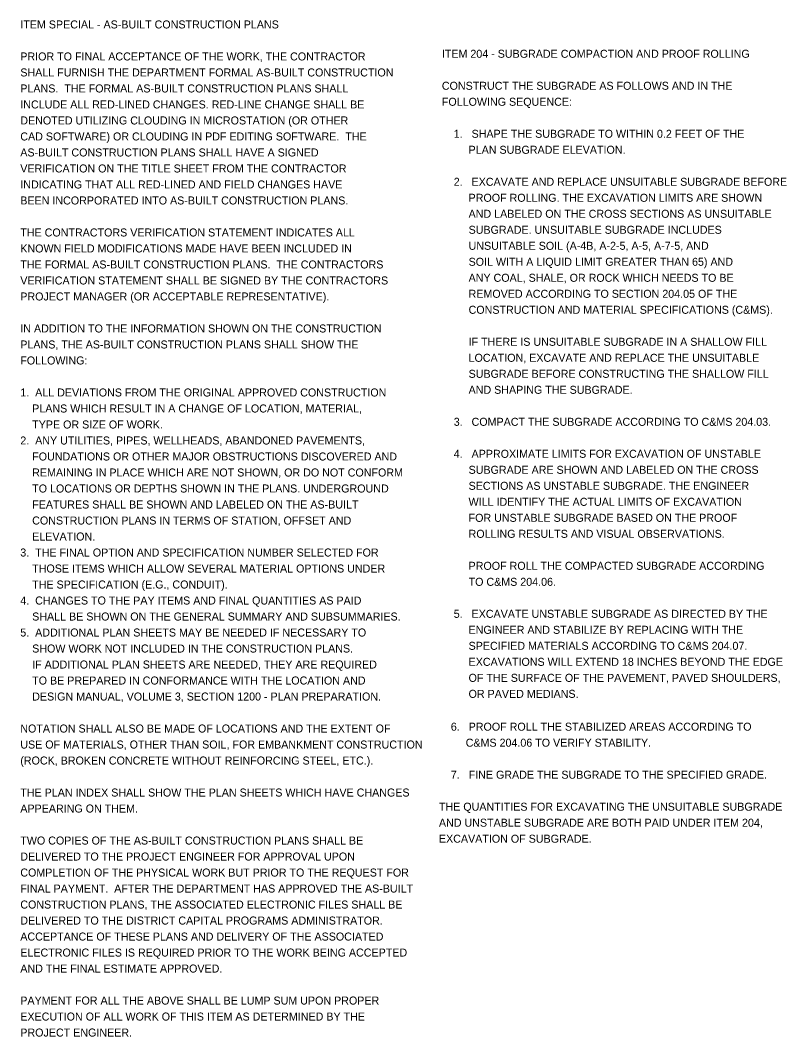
# Model space of a CAD drawing. Extents: x -17.1 to 50.1, y -5.2 to 23.
# Drawn here: x 36.64 to 50.06, y 3.36 to 21.14 of the extents above; entities that cross this region are included whole.
import ezdxf

# ---------------------------------------------------------------- set-up
doc = ezdxf.new("R2010")
doc.units = 0
doc.layers.add('SH_Text', color=7, linetype='Continuous')

msp = doc.modelspace()

# ---------------------------------------------------------------- texts
at = {"layer": 'SH_Text'}
for s, p in [('ITEM SPECIAL - AS-BUILT CONSTRUCTION PLANS', (36.64, 21)), ('PRIOR TO FINAL ACCEPTANCE OF THE WORK, THE CONTRACTOR', (36.64, 20.44)), ('ITEM 204 - SUBGRADE COMPACTION AND PROOF ROLLING', (44.019, 20.487)), ('SHALL FURNISH THE DEPARTMENT FORMAL AS-BUILT CONSTRUCTION', (36.64, 20.16)), ('PLANS.  THE FORMAL AS-BUILT CONSTRUCTION PLANS SHALL', (36.64, 19.88)), ('CONSTRUCT THE SUBGRADE AS FOLLOWS AND IN THE', (44.019, 19.927)), ('INCLUDE ALL RED-LINED CHANGES. RED-LINE CHANGE SHALL BE', (36.64, 19.6)), ('FOLLOWING SEQUENCE:', (44.019, 19.647)), ('DENOTED UTILIZING CLOUDING IN MICROSTATION (OR OTHER', (36.64, 19.32)), ('    1.   SHAPE THE SUBGRADE TO WITHIN 0.2 FEET OF THE', (44.019, 19.087)), ('CAD SOFTWARE) OR CLOUDING IN PDF EDITING SOFTWARE.  THE', (36.64, 19.04)), ('AS-BUILT CONSTRUCTION PLANS SHALL HAVE A SIGNED', (36.64, 18.76)), ('         PLAN SUBGRADE ELEVATION.', (44.019, 18.807)), ('VERIFICATION ON THE TITLE SHEET FROM THE CONTRACTOR', (36.64, 18.48)), ('INDICATING THAT ALL RED-LINED AND FIELD CHANGES HAVE', (36.64, 18.2)), ('    2.   EXCAVATE AND REPLACE UNSUITABLE SUBGRADE BEFORE', (44.019, 18.247)), ('BEEN INCORPORATED INTO AS-BUILT CONSTRUCTION PLANS.', (36.64, 17.92)), ('         PROOF ROLLING. THE EXCAVATION LIMITS ARE SHOWN', (44.019, 17.967)), ('         AND LABELED ON THE CROSS SECTIONS AS UNSUITABLE', (44.019, 17.687)), ('THE CONTRACTORS VERIFICATION STATEMENT INDICATES ALL', (36.64, 17.36)), ('         SUBGRADE. UNSUITABLE SUBGRADE INCLUDES', (44.019, 17.407)), ('         UNSUITABLE SOIL (A-4B, A-2-5, A-5, A-7-5, AND', (44.019, 17.127)), ('KNOWN FIELD MODIFICATIONS MADE HAVE BEEN INCLUDED IN', (36.64, 17.08)), ('THE FORMAL AS-BUILT CONSTRUCTION PLANS.  THE CONTRACTORS', (36.64, 16.8)), ('         SOIL WITH A LIQUID LIMIT GREATER THAN 65) AND', (44.019, 16.847)), ('VERIFICATION STATEMENT SHALL BE SIGNED BY THE CONTRACTORS', (36.64, 16.52)), ('         ANY COAL, SHALE, OR ROCK WHICH NEEDS TO BE', (44.019, 16.567)), ('PROJECT MANAGER (OR ACCEPTABLE REPRESENTATIVE).', (36.64, 16.24)), ('         REMOVED ACCORDING TO SECTION 204.05 OF THE', (44.019, 16.287)), ('         CONSTRUCTION AND MATERIAL SPECIFICATIONS (C&MS).', (44.019, 16.007)), ('IN ADDITION TO THE INFORMATION SHOWN ON THE CONSTRUCTION', (36.64, 15.68)), ('PLANS, THE AS-BUILT CONSTRUCTION PLANS SHALL SHOW THE', (36.64, 15.4)), ('         IF THERE IS UNSUITABLE SUBGRADE IN A SHALLOW FILL', (44.019, 15.447)), ('         LOCATION, EXCAVATE AND REPLACE THE UNSUITABLE', (44.019, 15.167)), ('FOLLOWING:', (36.64, 15.12)), ('         SUBGRADE BEFORE CONSTRUCTING THE SHALLOW FILL', (44.019, 14.887)), ('1.  ALL DEVIATIONS FROM THE ORIGINAL APPROVED CONSTRUCTION', (36.64, 14.56)), ('         AND SHAPING THE SUBGRADE.', (44.019, 14.607)), ('    PLANS WHICH RESULT IN A CHANGE OF LOCATION, MATERIAL,', (36.64, 14.28)), ('    TYPE OR SIZE OF WORK.', (36.64, 14)), ('    3.   COMPACT THE SUBGRADE ACCORDING TO C&MS 204.03.', (44.019, 14.047)), ('2.  ANY UTILITIES, PIPES, WELLHEADS, ABANDONED PAVEMENTS,', (36.64, 13.72)), ('    FOUNDATIONS OR OTHER MAJOR OBSTRUCTIONS DISCOVERED AND', (36.64, 13.44)), ('    4.   APPROXIMATE LIMITS FOR EXCAVATION OF UNSTABLE', (44.019, 13.487)), ('         SUBGRADE ARE SHOWN AND LABELED ON THE CROSS', (44.019, 13.207)), ('    REMAINING IN PLACE WHICH ARE NOT SHOWN, OR DO NOT CONFORM', (36.64, 13.16)), ('    TO LOCATIONS OR DEPTHS SHOWN IN THE PLANS. UNDERGROUND', (36.64, 12.88)), ('         SECTIONS AS UNSTABLE SUBGRADE. THE ENGINEER', (44.019, 12.927)), ('    FEATURES SHALL BE SHOWN AND LABELED ON THE AS-BUILT', (36.64, 12.6)), ('         WILL IDENTIFY THE ACTUAL LIMITS OF EXCAVATION', (44.019, 12.647)), ('    CONSTRUCTION PLANS IN TERMS OF STATION, OFFSET AND', (36.64, 12.32)), ('         FOR UNSTABLE SUBGRADE BASED ON THE PROOF', (44.019, 12.367)), ('    ELEVATION.', (36.64, 12.04)), ('         ROLLING RESULTS AND VISUAL OBSERVATIONS.', (44.019, 12.087)), ('3.  THE FINAL OPTION AND SPECIFICATION NUMBER SELECTED FOR', (36.64, 11.76)), ('    THOSE ITEMS WHICH ALLOW SEVERAL MATERIAL OPTIONS UNDER', (36.64, 11.48)), ('         PROOF ROLL THE COMPACTED SUBGRADE ACCORDING', (44.019, 11.527)), ('         TO C&MS 204.06.', (44.019, 11.247)), ('    THE SPECIFICATION (E.G., CONDUIT).', (36.64, 11.2)), ('4.  CHANGES TO THE PAY ITEMS AND FINAL QUANTITIES AS PAID', (36.64, 10.92)), ('    SHALL BE SHOWN ON THE GENERAL SUMMARY AND SUBSUMMARIES.', (36.64, 10.64)), ('    5.   EXCAVATE UNSTABLE SUBGRADE AS DIRECTED BY THE', (44.019, 10.687)), ('5.  ADDITIONAL PLAN SHEETS MAY BE NEEDED IF NECESSARY TO', (36.64, 10.36)), ('         ENGINEER AND STABILIZE BY REPLACING WITH THE', (44.019, 10.407)), ('    SHOW WORK NOT INCLUDED IN THE CONSTRUCTION PLANS.', (36.64, 10.08)), ('         SPECIFIED MATERIALS ACCORDING TO C&MS 204.07.', (44.019, 10.127)), ('         EXCAVATIONS WILL EXTEND 18 INCHES BEYOND THE EDGE', (44.019, 9.847)), ('    IF ADDITIONAL PLAN SHEETS ARE NEEDED, THEY ARE REQUIRED', (36.64, 9.8)), ('    TO BE PREPARED IN CONFORMANCE WITH THE LOCATION AND', (36.64, 9.52)), ('         OF THE SURFACE OF THE PAVEMENT, PAVED SHOULDERS,', (44.019, 9.567)), ('         OR PAVED MEDIANS.', (44.019, 9.287)), ('    DESIGN MANUAL, VOLUME 3, SECTION 1200 - PLAN PREPARATION.', (36.64, 9.24)), ('NOTATION SHALL ALSO BE MADE OF LOCATIONS AND THE EXTENT OF', (36.64, 8.68)), ('    6.   PROOF ROLL THE STABILIZED AREAS ACCORDING TO', (43.968, 8.712)), ('USE OF MATERIALS, OTHER THAN SOIL, FOR EMBANKMENT CONSTRUCTION', (36.64, 8.4)), ('         C&MS 204.06 TO VERIFY STABILITY.', (43.968, 8.432)), ('(ROCK, BROKEN CONCRETE WITHOUT REINFORCING STEEL, ETC.).', (36.64, 8.12)), ('    7.   FINE GRADE THE SUBGRADE TO THE SPECIFIED GRADE.', (43.968, 7.872)), ('THE PLAN INDEX SHALL SHOW THE PLAN SHEETS WHICH HAVE CHANGES', (36.64, 7.56)), ('APPEARING ON THEM.', (36.64, 7.28)), ('THE QUANTITIES FOR EXCAVATING THE UNSUITABLE SUBGRADE', (43.968, 7.312)), ('AND UNSTABLE SUBGRADE ARE BOTH PAID UNDER ITEM 204,', (43.968, 7.032)), ('TWO COPIES OF THE AS-BUILT CONSTRUCTION PLANS SHALL BE', (36.64, 6.72)), ('EXCAVATION OF SUBGRADE.', (43.968, 6.752)), ('DELIVERED TO THE PROJECT ENGINEER FOR APPROVAL UPON', (36.64, 6.44)), ('COMPLETION OF THE PHYSICAL WORK BUT PRIOR TO THE REQUEST FOR', (36.64, 6.16)), ('FINAL PAYMENT.  AFTER THE DEPARTMENT HAS APPROVED THE AS-BUILT', (36.64, 5.88)), ('CONSTRUCTION PLANS, THE ASSOCIATED ELECTRONIC FILES SHALL BE', (36.64, 5.6)), ('DELIVERED TO THE DISTRICT CAPITAL PROGRAMS ADMINISTRATOR.', (36.64, 5.32)), ('ACCEPTANCE OF THESE PLANS AND DELIVERY OF THE ASSOCIATED', (36.64, 5.04)), ('ELECTRONIC FILES IS REQUIRED PRIOR TO THE WORK BEING ACCEPTED', (36.64, 4.76)), ('AND THE FINAL ESTIMATE APPROVED.', (36.64, 4.48)), ('PAYMENT FOR ALL THE ABOVE SHALL BE LUMP SUM UPON PROPER', (36.64, 3.92)), ('EXECUTION OF ALL WORK OF THIS ITEM AS DETERMINED BY THE', (36.64, 3.64)), ('PROJECT ENGINEER.', (36.64, 3.36))]:
    msp.add_text(s, height=0.14, dxfattribs=at).set_placement(p)

doc.saveas('drawing.dxf')
